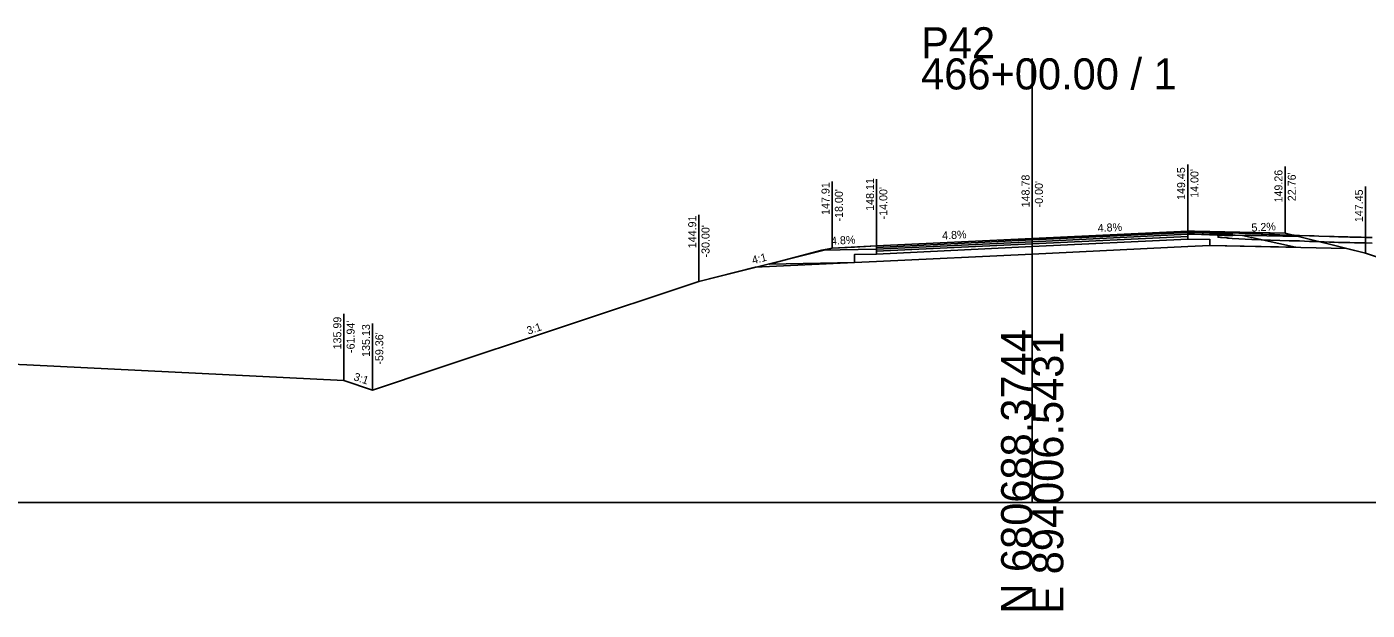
# Model space of a CAD drawing. Extents: x -26 to 4403, y -13 to 9578.
# Drawn here: x 1159.5 to 1280.1, y 7990.3 to 8042.8 of the extents above; entities that cross this region are included whole.
import ezdxf

# ---------------------------------------------------------------- set-up
doc = ezdxf.new("R2010")
doc.units = 0
for name, color, linetype in [('_CIVIL_CONSTRUCTION', 7, 'Continuous'), ('ASPHALT_19MM1', 7, 'Continuous'), ('ASPHALT_19MM2', 7, 'Continuous'), ('ASPHALT_9_5MM1', 7, 'Continuous'), ('CONST_DCH', 7, 'Continuous'), ('CONST_LV3', 7, 'Continuous'), ('Default', 7, 'Continuous'), ('DTM_CORRIDOR', 7, 'Continuous'), ('DTM_P_FINISHED_GRADE', 7, 'Continuous'), ('DTM_TEMP_DROP', 7, 'Continuous'), ('DTM_X_GROUND', 7, 'Continuous'), ('SLOPE_STAKES_FILL', 7, 'Continuous'), ('XS_CELL', 7, 'Continuous'), ('XS_P_ASPHALT', 7, 'Continuous'), ('XS_P_CRUSHED_STONE', 7, 'Continuous'), ('XS_P_DR_ASPHALT', 7, 'Continuous'), ('XS_P_DR_ASPHALT_B', 7, 'Continuous'), ('XS_P_DR_GRAVEL', 7, 'Continuous'), ('XS_P_GROUND', 7, 'Continuous'), ('XS_P_SHOULDER', 7, 'Continuous'), ('XS_P_SUBGRADE_GRANULAR', 7, 'Continuous'), ('XS_P_TX_CLEARZONE', 7, 'Continuous'), ('XS_P_TX_FS_BS', 7, 'Continuous')]:
    doc.layers.add(name, color=color, linetype=linetype)

msp = doc.modelspace()

# ---------------------------------------------------------------- linework, layer by layer
at = {"layer": 'ASPHALT_19MM1'}
for points in [[(1250, 8023.49), (1236, 8022.81), (1236, 8022.81), (1236, 8022.63), (1250, 8023.3), (1250, 8023.3), (1250, 8023.49), (1250, 8023.49), (1250, 8023.49)], [(1264, 8024.16), (1250, 8023.49), (1250, 8023.49), (1250, 8023.3), (1264, 8023.97), (1264, 8023.97), (1264, 8024.16), (1264, 8024.16), (1264, 8024.16)]]:
    msp.add_lwpolyline(points, dxfattribs=at)
at = {"layer": 'ASPHALT_19MM2'}
for points in [[(1250, 8023.3), (1236, 8022.63), (1236, 8022.63), (1236, 8022.38), (1250, 8023.05), (1250, 8023.05), (1250, 8023.3), (1250, 8023.3), (1250, 8023.3)], [(1264, 8023.97), (1250, 8023.3), (1250, 8023.3), (1250, 8023.05), (1264, 8023.72), (1264, 8023.72), (1264, 8023.97), (1264, 8023.97), (1264, 8023.97)]]:
    msp.add_lwpolyline(points, dxfattribs=at)
at = {"layer": 'ASPHALT_9_5MM1'}
for points in [[(1264, 8024.45), (1250, 8023.78), (1250, 8023.78), (1250, 8023.65), (1264, 8024.33), (1264, 8024.33), (1264, 8024.45), (1264, 8024.45), (1264, 8024.45)], [(1250, 8023.78), (1236, 8023.11), (1236, 8023.11), (1236, 8022.98), (1250, 8023.65), (1250, 8023.65), (1250, 8023.78), (1250, 8023.78), (1250, 8023.78)]]:
    msp.add_lwpolyline(points, dxfattribs=at)
at = {"layer": 'CONST_LV3'}
for points in [[(1264, 8024.45), (1264.31, 8024.44), (1264.52, 8024.44), (1270.77, 8024.16), (1271.28, 8024.15), (1271.79, 8024.14), (1272.65, 8024.09), (1273.11, 8024.08), (1273.57, 8024.07), (1274.04, 8024.06), (1274.94, 8024.02), (1275.37, 8024.01), (1275.8, 8024), (1276.76, 8023.96), (1277.18, 8023.95), (1277.56, 8023.93), (1277.97, 8023.92), (1278, 8023.92), (1278.41, 8023.92), (1279, 8023.9), (1279.59, 8023.89), (1280, 8023.88), (1280, 8023.88), (1280, 8023.88), (1280.59, 8023.86)], [(1280, 8022.45), (1280, 8022.45), (1278.27, 8022.88)], [(1225.08, 8021.19), (1220, 8019.91)]]:
    msp.add_lwpolyline(points, dxfattribs=at)
at = {"layer": 'Default'}
for points in [[(1264, 8024.33), (1250, 8023.65), (1250, 8023.65), (1250, 8023.49), (1264, 8024.16), (1264, 8024.16), (1264, 8024.33), (1264, 8024.33), (1264, 8024.33)], [(1250, 8023.65), (1236, 8022.98), (1236, 8022.98), (1236, 8022.81), (1250, 8023.49), (1250, 8023.49), (1250, 8023.65), (1250, 8023.65), (1250, 8023.65)]]:
    msp.add_lwpolyline(points, dxfattribs=at)
at = {"layer": 'DTM_P_FINISHED_GRADE'}
for points in [[(1264, 8024.45), (1264.62, 8024.43), (1268, 8024.28)], [(1266.73, 8024.39), (1266.76, 8024.39), (1266.93, 8024.39), (1266.96, 8024.38), (1266.98, 8024.38), (1266.98, 8024.38), (1266.99, 8024.38), (1267, 8024.38), (1267.05, 8024.38), (1267.07, 8024.38), (1267.11, 8024.37), (1267.5, 8024.33), (1267.53, 8024.33), (1267.54, 8024.33), (1267.54, 8024.33), (1267.57, 8024.33), (1267.58, 8024.32), (1267.61, 8024.32), (1267.64, 8024.32), (1267.65, 8024.32), (1267.67, 8024.32), (1267.69, 8024.31), (1267.7, 8024.31), (1267.73, 8024.31), (1268, 8024.28), (1269.78, 8024.2), (1273.11, 8024.08), (1273.57, 8024.07), (1273.58, 8024.07), (1274.04, 8024.06), (1274.94, 8024.02), (1274.94, 8024.02), (1275.37, 8024.01), (1275.38, 8024.01), (1275.8, 8024), (1276.76, 8023.96), (1276.77, 8023.96), (1277.18, 8023.95), (1277.18, 8023.95), (1277.56, 8023.93), (1277.97, 8023.92), (1278, 8023.92), (1278, 8023.92), (1278.59, 8023.91), (1279, 8023.9), (1279, 8023.9), (1279.59, 8023.89), (1280, 8023.88), (1280, 8023.88), (1280, 8023.88), (1280.59, 8023.86)]]:
    msp.add_lwpolyline(points, dxfattribs=at)
at = {"layer": 'DTM_X_GROUND'}
for p, q in [((1159.52, 8012.39), (1140.86, 8013.33)), ((1188.06, 8010.99), (1159.52, 8012.39))]:
    msp.add_line(p, q, dxfattribs=at)
at = {"layer": 'XS_CELL'}
for p, q in [((1250, 8000), (1250, 8040)), ((1000, 8000), (1250, 8000)), ((1250, 8000), (1400, 8000))]:
    msp.add_line(p, q, dxfattribs=at)
at = {"layer": 'XS_P_ASPHALT'}
msp.add_lwpolyline([(1250, 8023.78), (1236, 8023.11), (1236, 8023.11), (1236, 8022.38), (1250, 8023.05), (1250, 8023.05), (1264, 8023.72), (1264, 8023.72), (1264, 8024.45), (1264, 8024.45), (1264, 8024.45), (1250, 8023.78), (1250, 8023.78)], dxfattribs=at)
at = {"layer": 'XS_P_CRUSHED_STONE'}
for p, q in [((1266, 8024.41), (1264, 8024.45)), ((1264, 8024.45), (1264, 8024.45)), ((1264, 8024.45), (1264, 8024.45)), ((1264, 8024.45), (1264, 8024.16)), ((1272.76, 8024.26), (1266, 8024.41)), ((1272.76, 8024.26), (1272.76, 8024.26)), ((1272.76, 8024.26), (1272.76, 8024.26)), ((1272.76, 8024.26), (1273.95, 8023.96)), ((1264, 8024.16), (1264, 8024.16)), ((1264, 8024.16), (1273.95, 8023.96))]:
    msp.add_line(p, q, dxfattribs=at)
for points in [[(1234, 8023.01), (1232, 8022.91), (1232, 8022.91), (1231.08, 8022.72), (1236, 8022.81), (1236, 8022.81), (1236, 8023.11), (1236, 8023.11), (1236, 8023.11), (1234, 8023.01), (1234, 8023.01)], [(1236, 8021.71), (1234, 8021.61), (1234, 8022.33), (1234, 8022.33), (1236, 8022.38), (1236, 8022.38), (1250, 8023.05), (1250, 8023.05), (1250, 8023.05), (1250, 8022.38), (1250, 8022.38), (1236, 8021.71), (1236, 8021.71)], [(1266, 8023.15), (1266, 8023.15), (1266, 8023.68), (1266, 8023.68), (1264, 8023.72), (1264, 8023.72), (1264, 8023.72), (1250, 8023.05), (1250, 8023.05), (1250, 8022.38), (1264, 8023.05), (1264, 8023.05), (1266, 8023.15)]]:
    msp.add_lwpolyline(points, dxfattribs=at)
at = {"layer": 'XS_P_DR_ASPHALT'}
msp.add_lwpolyline([(1264, 8024.45), (1264, 8024.33), (1264.62, 8024.31), (1268, 8024.16), (1268, 8024.28), (1264.62, 8024.43), (1264, 8024.45)], dxfattribs=at)
at = {"layer": 'XS_P_DR_ASPHALT_B'}
msp.add_lwpolyline([(1264, 8024.33), (1264, 8024.2), (1264.62, 8024.18), (1268, 8024.03), (1268, 8024.16), (1264.62, 8024.31), (1264, 8024.33)], dxfattribs=at)
at = {"layer": 'XS_P_DR_GRAVEL'}
for points in [[(1266.73, 8024.39), (1266.73, 8023.89), (1266.76, 8023.89), (1266.93, 8023.89), (1266.96, 8023.88), (1266.98, 8023.88), (1266.98, 8023.88), (1266.99, 8023.88), (1267, 8023.88), (1267.05, 8023.88), (1267.07, 8023.88), (1267.11, 8023.87), (1267.5, 8023.83), (1267.53, 8023.83), (1267.54, 8023.83), (1267.54, 8023.83), (1267.57, 8023.83), (1267.58, 8023.82), (1267.61, 8023.82), (1267.64, 8023.82), (1267.65, 8023.82), (1267.67, 8023.82), (1267.69, 8023.81), (1267.7, 8023.81), (1267.73, 8023.81), (1268, 8023.78), (1269.78, 8023.7), (1273.11, 8023.58), (1273.57, 8023.57), (1273.58, 8023.57), (1274.04, 8023.56), (1274.94, 8023.52), (1274.94, 8023.52), (1275.37, 8023.51), (1275.38, 8023.51), (1275.8, 8023.5), (1276.76, 8023.46), (1276.77, 8023.46), (1277.18, 8023.45), (1277.18, 8023.45), (1277.56, 8023.43), (1277.97, 8023.42), (1278, 8023.42), (1278, 8023.42), (1278.59, 8023.41), (1279, 8023.4), (1279, 8023.4), (1279.59, 8023.39), (1280, 8023.38), (1280, 8023.38), (1280, 8023.38), (1280.59, 8023.36)], [(1280.59, 8023.86), (1280, 8023.88), (1280, 8023.88), (1280, 8023.88), (1279.59, 8023.89), (1279, 8023.9), (1279, 8023.9), (1278.59, 8023.91), (1278, 8023.92), (1278, 8023.92), (1277.97, 8023.92), (1277.56, 8023.93), (1277.18, 8023.95), (1277.18, 8023.95), (1276.77, 8023.96), (1276.76, 8023.96), (1275.8, 8024), (1275.38, 8024.01), (1275.37, 8024.01), (1274.94, 8024.02), (1274.94, 8024.02), (1274.04, 8024.06), (1273.58, 8024.07), (1273.57, 8024.07), (1273.11, 8024.08), (1269.78, 8024.2), (1268, 8024.28), (1267.73, 8024.31), (1267.7, 8024.31), (1267.69, 8024.31), (1267.67, 8024.32), (1267.65, 8024.32), (1267.64, 8024.32), (1267.61, 8024.32), (1267.58, 8024.32), (1267.57, 8024.33), (1267.54, 8024.33), (1267.54, 8024.33), (1267.53, 8024.33), (1267.5, 8024.33), (1267.11, 8024.37), (1267.07, 8024.38), (1267.05, 8024.38), (1267, 8024.38), (1266.99, 8024.38), (1266.98, 8024.38), (1266.98, 8024.38), (1266.96, 8024.38), (1266.93, 8024.39), (1266.76, 8024.39), (1266.73, 8024.39)]]:
    msp.add_lwpolyline(points, dxfattribs=at)
at = {"layer": 'XS_P_GROUND'}
for points in [[(1302.58, 8014.92), (1302.58, 8014.92), (1280, 8022.45), (1280, 8022.45), (1272.76, 8024.26)], [(1232, 8022.91), (1220, 8019.91), (1195.83, 8011.86), (1191.26, 8010.34), (1190.64, 8010.13)], [(1190.64, 8010.13), (1188.06, 8010.99), (1188.06, 8010.99), (1188.06, 8010.99)]]:
    msp.add_lwpolyline(points, dxfattribs=at)
at = {"layer": 'XS_P_SHOULDER'}
for points in [[(1272.76, 8024.26), (1272.76, 8024.26), (1264, 8024.45)], [(1232, 8022.91), (1236, 8023.11), (1236, 8023.11)]]:
    msp.add_lwpolyline(points, dxfattribs=at)
at = {"layer": 'XS_P_SUBGRADE_GRANULAR'}
for points in [[(1264, 8023.05), (1264, 8023.05), (1250, 8022.38)], [(1264, 8024.16), (1264, 8023.72), (1264, 8023.72), (1266, 8023.68), (1266, 8023.68), (1266, 8023.15), (1266, 8023.15), (1273.7, 8023), (1268.92, 8024.06), (1268.92, 8024.06), (1264, 8024.16), (1264, 8024.16), (1264, 8024.16)], [(1278.27, 8022.88), (1278.27, 8022.88), (1266, 8023.15), (1266, 8023.15), (1264, 8023.05)], [(1236, 8022.81), (1236, 8022.81), (1236, 8022.81), (1231.08, 8022.72), (1231.08, 8022.72), (1226.33, 8021.47), (1234, 8021.61), (1234, 8021.61), (1234, 8022.33), (1234, 8022.33), (1236, 8022.38), (1236, 8022.38), (1236, 8022.81)], [(1236, 8021.71), (1250, 8022.38), (1250, 8022.38)], [(1225.08, 8021.19), (1234, 8021.61), (1234, 8021.61), (1236, 8021.71), (1236, 8021.71)]]:
    msp.add_lwpolyline(points, dxfattribs=at)
at = {"layer": 'XS_P_TX_CLEARZONE'}
for p, q in [((1264, 8024.45), (1264, 8030.45)), ((1236, 8023.11), (1236, 8029.11)), ((1250, 8023.78), (1250, 8029.78)), ((1272.76, 8024.26), (1272.76, 8030.26)), ((1232, 8022.91), (1232, 8028.91)), ((1280, 8022.45), (1280, 8028.45)), ((1220, 8019.91), (1220, 8025.91)), ((1188.06, 8010.99), (1188.06, 8016.99)), ((1190.64, 8010.13), (1190.64, 8016.13))]:
    msp.add_line(p, q, dxfattribs=at)

# ---------------------------------------------------------------- texts
at = {"layer": '_CIVIL_CONSTRUCTION'}
for p in [(1263.96, 8024.39), (1233.96, 8022.95), (1235.96, 8023.05), (1249.96, 8023.72), (1265.96, 8023.62), (1268.88, 8024), (1231.04, 8022.66), (1233.97, 8022.27)]:
    msp.add_text('X', height=0.12, dxfattribs=at).set_placement(p)
at = {"layer": 'CONST_DCH'}
msp.add_text('X', height=0.12, dxfattribs=at).set_placement((1190.61, 8010.07))
at = {"layer": 'DTM_CORRIDOR'}
msp.add_text('X', height=0.12, dxfattribs=at).set_placement((1188.02, 8010.93))
at = {"layer": 'DTM_TEMP_DROP'}
for p in [(1272.72, 8024.2), (1231.96, 8022.85)]:
    msp.add_text('X', height=0.12, dxfattribs=at).set_placement(p)
at = {"layer": 'SLOPE_STAKES_FILL'}
for p in [(1279.96, 8022.39), (1219.96, 8019.85)]:
    msp.add_text('X', height=0.12, dxfattribs=at).set_placement(p)
at = {"layer": 'XS_CELL'}
for s, p in [('P42', (1240, 8040)), ('466+00.00 / 1', (1240, 8037.2))]:
    msp.add_text(s, height=2.8, dxfattribs=at).set_placement(p)
for s, p in [('N 680688.3744', (1250, 7990)), ('E 894006.5431', (1252.8, 7990))]:
    msp.add_text(s, height=2.8, rotation=90, dxfattribs=at).set_placement(p)
at = {"layer": 'XS_P_TX_CLEARZONE'}
for s, p in [('148.11', (1235.76, 8026.27)), ('148.78', (1249.76, 8026.58)), ('149.45', (1263.76, 8027.25)), ("14.00'", (1264.96, 8027.44)), ('149.26', (1272.52, 8027.02)), ("22.76'", (1273.72, 8027.14)), ('147.91', (1231.76, 8025.9)), ("-18.00'", (1232.96, 8025.31)), ("-14.00'", (1236.96, 8025.5)), ("-0.00'", (1250.96, 8026.58)), ('147.45', (1279.76, 8025.25)), ('144.91', (1219.76, 8022.9)), ("-30.00'", (1220.96, 8022.07)), ('135.99', (1187.82, 8013.79)), ("-61.94'", (1189.02, 8013.47)), ('135.13', (1190.4, 8013.12)), ("-59.36'", (1191.6, 8012.42))]:
    msp.add_text(s, height=0.72, rotation=90, dxfattribs=at).set_placement(p)
at = {"layer": 'XS_P_TX_FS_BS'}
for s, rotation, p in [('4.8%', 2.7481, (1241.91, 8023.69)), ('4.8%', 2.7481, (1255.91, 8024.36)), ('5.2%', 2.9538, (1269.75, 8024.4)), ('4.8%', 2.7481, (1231.91, 8023.21)), ('4:1', 14.1906, (1224.87, 8021.46)), ('3:1', 18.4332, (1204.65, 8015.11)), ('3:1', 341.5651, (1188.87, 8011.04))]:
    msp.add_text(s, height=0.72, rotation=rotation, dxfattribs=at).set_placement(p)

doc.saveas('drawing.dxf')
